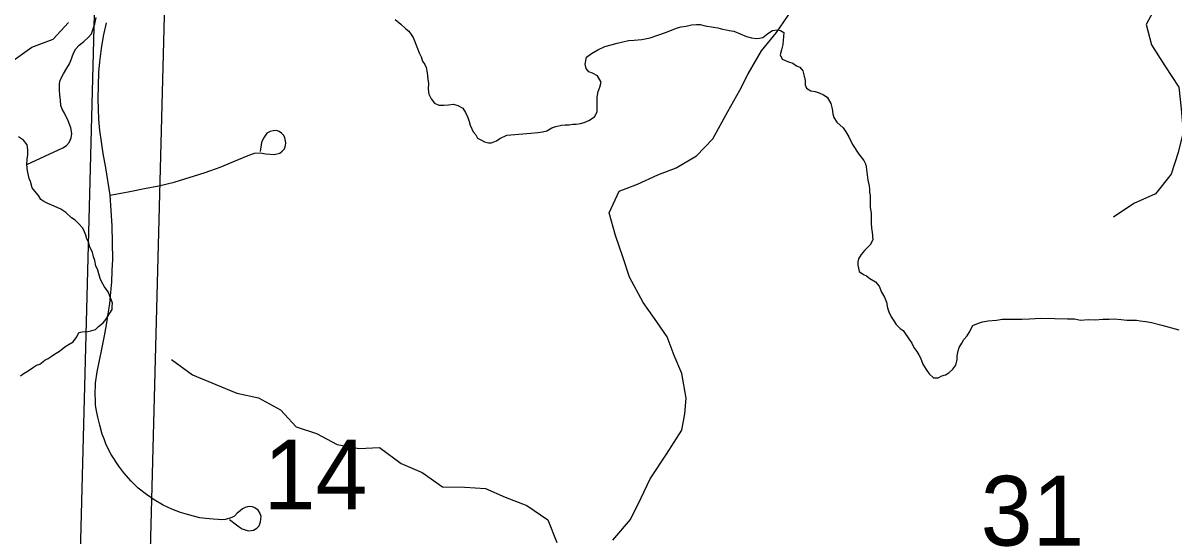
# Model space of a CAD drawing. Extents: x -21.1 to 50.3, y 0 to 22.1.
# Drawn here: x 2.692 to 3.383, y 19.37 to 19.678 of the extents above; entities that cross this region are included whole.
import ezdxf

# ---------------------------------------------------------------- set-up
doc = ezdxf.new("R2010")
doc.units = 0
for name, color, linetype in [('GM_X_Minor_River', 7, 'Continuous'), ('GM_X_Section', 7, 'Continuous'), ('GM_X_Section_Text', 7, 'Continuous'), ('GM_X_Township_Road', 7, 'Continuous')]:
    doc.layers.add(name, color=color, linetype=linetype)

msp = doc.modelspace()

# ---------------------------------------------------------------- linework, layer by layer
at = {"layer": 'GM_X_Minor_River'}
for points in [[(3.39957, 19.77915), (3.39901, 19.77155), (3.39523, 19.75823), (3.38687, 19.74681), (3.38726, 19.7373), (3.38918, 19.72742), (3.39186, 19.71449), (3.38237, 19.70193), (3.37326, 19.68937), (3.36681, 19.67719), (3.36987, 19.66502), (3.37788, 19.65248), (3.38627, 19.63956), (3.38781, 19.62663), (3.38897, 19.61256), (3.38594, 19.60039), (3.38178, 19.58745), (3.37228, 19.57565), (3.35935, 19.56993), (3.34719, 19.56155)], [(3.04644, 19.36782), (3.05706, 19.38033), (3.06351, 19.39323), (3.06882, 19.40461), (3.07869, 19.4194), (3.08779, 19.43382), (3.08969, 19.44368), (3.09046, 19.45316), (3.08781, 19.46795), (3.08327, 19.47857), (3.0791, 19.48994), (3.07153, 19.50094), (3.06471, 19.51043), (3.05638, 19.52559), (3.05259, 19.53735), (3.04805, 19.55062), (3.04427, 19.56428), (3.05034, 19.57718), (3.06133, 19.58135), (3.07347, 19.58704), (3.08446, 19.59121), (3.0966, 19.59842), (3.10646, 19.60866), (3.11556, 19.62497), (3.12277, 19.63787), (3.1277, 19.64773), (3.13567, 19.66138), (3.14477, 19.67238), (3.1535, 19.68528)], [(2.68421, 19.65412), (2.69748, 19.6636), (2.71037, 19.66853), (2.71947, 19.6784)], [(2.69461, 19.59333), (2.71609, 19.60318), (2.7184, 19.60466), (2.71995, 19.60652), (2.72114, 19.60916), (2.72157, 19.61181), (2.72088, 19.61524), (2.71943, 19.61945), (2.71724, 19.62405), (2.71576, 19.62635), (2.71504, 19.62864), (2.71472, 19.63169), (2.7144, 19.63511), (2.71407, 19.63778), (2.71411, 19.63967), (2.71414, 19.64157), (2.71457, 19.64384), (2.71654, 19.64761), (2.7185, 19.65099), (2.72007, 19.65362), (2.72127, 19.65663), (2.72206, 19.65851), (2.72286, 19.6604), (2.72404, 19.66266), (2.72599, 19.6649), (2.72869, 19.66713), (2.73139, 19.66936), (2.73334, 19.6716), (2.73535, 19.67764), (2.73618, 19.68142)], [(2.91565, 19.68014), (2.91904, 19.67743), (2.92205, 19.67472), (2.92393, 19.67318), (2.92542, 19.67126), (2.92654, 19.66934), (2.92727, 19.66743), (2.93021, 19.66016), (2.93132, 19.65786), (2.93205, 19.65519), (2.93354, 19.65326), (2.93428, 19.65135), (2.935, 19.6483), (2.93532, 19.64449), (2.93567, 19.64183), (2.93562, 19.6384), (2.93596, 19.63536), (2.93745, 19.63267), (2.93931, 19.62998), (2.94195, 19.62881), (2.945, 19.62876), (2.94766, 19.62911), (2.95071, 19.62945), (2.95337, 19.62865), (2.95639, 19.62709), (2.95787, 19.6244), (2.95935, 19.62134), (2.96008, 19.61905), (2.96081, 19.61676), (2.96266, 19.61293), (2.96415, 19.61101), (2.96527, 19.60909), (2.96753, 19.60792), (2.96942, 19.60675), (2.9717, 19.60634), (2.9736, 19.60631), (2.97666, 19.60741), (2.97858, 19.6089), (2.98279, 19.61075), (2.99726, 19.61207), (3.00145, 19.61239), (3.00412, 19.61274), (3.00679, 19.61346), (3.00986, 19.61532), (3.01215, 19.61605), (3.01558, 19.61676), (3.01787, 19.61711), (3.02015, 19.61708), (3.02244, 19.61743), (3.02434, 19.6174), (3.02701, 19.61775), (3.0293, 19.61848), (3.03198, 19.61958), (3.03543, 19.62181), (3.03699, 19.62484), (3.03702, 19.62712), (3.03707, 19.63054), (3.03711, 19.63358), (3.03754, 19.637), (3.03872, 19.63965), (3.03952, 19.64268), (3.03729, 19.64651), (3.03427, 19.64808), (3.032, 19.64887), (3.0305, 19.65079), (3.02978, 19.65346), (3.03059, 19.65764), (3.03367, 19.65987), (3.0375, 19.6621), (3.04171, 19.66395), (3.04553, 19.66504), (3.04897, 19.66613), (3.0524, 19.66684), (3.05584, 19.66756), (3.05926, 19.66789), (3.06383, 19.66821), (3.06879, 19.66928), (3.07338, 19.67074), (3.07873, 19.67257), (3.08217, 19.67404), (3.08523, 19.67514), (3.08752, 19.67587), (3.09057, 19.67621), (3.09362, 19.67693), (3.09667, 19.67726), (3.09895, 19.67723), (3.10198, 19.67643), (3.10691, 19.6756), (3.10957, 19.67518), (3.11222, 19.67439), (3.1145, 19.67398), (3.1164, 19.67357), (3.11905, 19.67315), (3.12283, 19.67158)], [(3.12283, 19.67158), (3.12662, 19.67), (3.12965, 19.6692), (3.13269, 19.66878), (3.13459, 19.66913), (3.1365, 19.66949), (3.13957, 19.67173), (3.14226, 19.67359), (3.14531, 19.67393), (3.1472, 19.67353), (3.14909, 19.67236), (3.14861, 19.66514), (3.14781, 19.66211), (3.14701, 19.65907), (3.14811, 19.6564), (3.15189, 19.65482), (3.15454, 19.65403), (3.15681, 19.65247), (3.1587, 19.65169), (3.16057, 19.64938), (3.16128, 19.64633), (3.16201, 19.64365), (3.16197, 19.64099), (3.16271, 19.63908), (3.16535, 19.63752), (3.16801, 19.6371), (3.17028, 19.63631), (3.17292, 19.63513), (3.17518, 19.63358), (3.17741, 19.62975), (3.17813, 19.62669), (3.17847, 19.62365), (3.1792, 19.62136), (3.18106, 19.61867), (3.18482, 19.61519), (3.18631, 19.61289), (3.18817, 19.60982), (3.19039, 19.60523), (3.19411, 19.59947), (3.1971, 19.59562), (3.19822, 19.59371), (3.19857, 19.5918), (3.1996, 19.5838), (3.20032, 19.58036), (3.20067, 19.57846), (3.20065, 19.57656), (3.201, 19.57465), (3.20096, 19.57161), (3.2009, 19.56743), (3.20162, 19.56399), (3.20157, 19.56095), (3.20154, 19.55829), (3.20187, 19.55486), (3.20222, 19.55257), (3.20254, 19.54801), (3.20097, 19.54498), (3.1975, 19.54161), (3.19557, 19.53935), (3.19402, 19.53671), (3.19361, 19.53482), (3.19358, 19.53291), (3.19394, 19.53101), (3.19429, 19.5291), (3.19692, 19.52716), (3.19882, 19.52638), (3.2007, 19.52483), (3.20409, 19.52288), (3.20634, 19.52019), (3.20781, 19.51674), (3.20967, 19.51367), (3.21077, 19.51062), (3.21149, 19.50718), (3.21222, 19.50489), (3.21369, 19.50183), (3.21518, 19.49953), (3.21667, 19.49722), (3.21892, 19.49491), (3.22081, 19.49374), (3.22192, 19.49183), (3.22603, 19.48606), (3.22713, 19.48339), (3.22901, 19.48108), (3.23012, 19.47916), (3.23123, 19.47724), (3.2327, 19.47342), (3.23456, 19.47035), (3.23643, 19.46766), (3.23906, 19.46534), (3.24172, 19.46531), (3.24402, 19.46642), (3.24631, 19.46715), (3.24823, 19.46826), (3.25054, 19.47051), (3.25247, 19.47277), (3.25328, 19.47618), (3.25331, 19.47846), (3.25373, 19.4815), (3.25452, 19.48339), (3.25608, 19.48603), (3.25725, 19.48829), (3.25918, 19.49055)], [(2.74115, 19.51992), (2.73931, 19.52299), (2.73858, 19.52491), (2.73787, 19.52758), (2.73715, 19.52987), (2.73606, 19.53255), (2.73536, 19.5356), (2.73464, 19.53789), (2.73393, 19.54056), (2.73247, 19.54363), (2.73176, 19.5463), (2.73066, 19.5486), (2.72994, 19.55089), (2.72922, 19.5528), (2.72812, 19.5551), (2.72551, 19.55781), (2.72364, 19.55975), (2.72139, 19.56131), (2.71803, 19.56441), (2.71502, 19.56636), (2.71088, 19.56834), (2.7071, 19.56993), (2.70484, 19.57111), (2.70297, 19.57228), (2.70149, 19.57459), (2.69926, 19.57729), (2.69777, 19.57922), (2.6967, 19.58303), (2.69598, 19.58494), (2.69492, 19.58952), (2.69461, 19.59333), (2.69467, 19.59636), (2.6951, 19.59901), (2.69516, 19.60205), (2.69483, 19.60509), (2.6926, 19.60779), (2.6896, 19.60975)], [(2.69073, 19.46655), (2.69303, 19.46803), (2.69534, 19.46951), (2.69804, 19.47135), (2.70035, 19.47283), (2.70226, 19.47355), (2.70535, 19.47578), (2.70727, 19.47688), (2.70919, 19.47798), (2.71112, 19.47947), (2.7142, 19.48131), (2.71728, 19.48391), (2.71997, 19.48538), (2.72228, 19.48685), (2.72462, 19.48985), (2.72581, 19.49248), (2.72772, 19.49283), (2.73114, 19.49314), (2.73305, 19.49349), (2.73573, 19.4942), (2.73766, 19.49606), (2.74036, 19.49829), (2.74192, 19.50016), (2.74584, 19.50616), (2.74587, 19.50806), (2.74591, 19.50996), (2.74519, 19.51225), (2.74337, 19.51684), (2.74115, 19.51992)], [(3.25918, 19.49055), (3.26035, 19.49244), (3.26269, 19.49659), (3.26613, 19.49806), (3.26842, 19.49879), (3.27186, 19.49951), (3.27681, 19.49982), (3.28024, 19.50053), (3.2829, 19.50049), (3.29203, 19.50037), (3.2966, 19.50069), (3.30345, 19.50097), (3.31181, 19.50086), (3.31942, 19.50075), (3.3236, 19.50069), (3.32739, 19.49988), (3.33196, 19.5002), (3.33615, 19.50014), (3.34072, 19.50046), (3.34452, 19.50041), (3.34757, 19.50074), (3.35174, 19.50031), (3.35516, 19.49988), (3.35859, 19.49983), (3.36087, 19.4998), (3.36314, 19.49939), (3.36656, 19.49896), (3.36998, 19.49854), (3.37604, 19.49693), (3.38627, 19.49413)], [(2.78136, 19.47634), (2.79401, 19.46707), (2.80811, 19.46125), (2.82068, 19.45615), (2.83359, 19.45334), (2.84696, 19.44599), (2.85622, 19.4359), (2.86839, 19.43194), (2.88099, 19.42533), (2.89389, 19.4229), (2.90637, 19.4235), (2.9194, 19.41386), (2.93198, 19.40839), (2.94423, 19.39987), (2.95747, 19.39972), (2.96997, 19.3988), (2.98179, 19.3937), (2.99474, 19.38861), (3.00737, 19.3801), (3.01291, 19.36654)]]:
    msp.add_lwpolyline(points, dxfattribs=at)
at = {"layer": 'GM_X_Section'}
for points in [[(3.82397, 20.01814), (3.83539, 19.00471), (3.80166, 19.0044), (2.75941, 19.00342), (2.78495, 19.98), (2.78619, 20.01563)], [(3.78068, 19.96762), (3.7921, 18.95419), (3.75837, 18.95389), (2.71612, 18.9529), (2.74167, 19.92948), (2.74291, 19.96511)]]:
    msp.add_lwpolyline(points, close=True, dxfattribs=at)
at = {"layer": 'GM_X_Township_Road'}
for points in [[(2.81617, 19.38037), (2.82045, 19.37702), (2.82204, 19.37586), (2.8239, 19.37472), (2.82567, 19.3741), (2.82744, 19.37357), (2.82925, 19.37359), (2.83071, 19.37383), (2.83266, 19.37498), (2.83399, 19.37655), (2.83454, 19.37772), (2.83496, 19.37897), (2.83513, 19.38047), (2.83523, 19.38206), (2.83452, 19.38427), (2.83345, 19.38586), (2.83151, 19.38737), (2.83, 19.38781), (2.82832, 19.38799), (2.82699, 19.3879), (2.82558, 19.38746), (2.82408, 19.38666), (2.82257, 19.38542), (2.82089, 19.384), (2.8193, 19.38233), (2.8177, 19.38153), (2.81594, 19.38082), (2.81356, 19.38033), (2.81151, 19.38011), (2.80939, 19.38021), (2.80644, 19.38041), (2.80196, 19.38089), (2.79842, 19.38136), (2.79453, 19.38218), (2.79098, 19.38325), (2.78674, 19.38443), (2.78155, 19.38643), (2.77636, 19.38891), (2.77093, 19.39198), (2.76633, 19.39528), (2.76149, 19.39905), (2.75713, 19.4033), (2.75276, 19.40825), (2.74969, 19.41226), (2.7451, 19.41922), (2.74332, 19.42265), (2.74203, 19.42571), (2.74109, 19.42797), (2.73984, 19.43152), (2.73831, 19.43695), (2.7371, 19.44161), (2.73631, 19.44541), (2.73587, 19.44886), (2.73569, 19.4524), (2.7356, 19.45487), (2.73587, 19.46213), (2.73684, 19.46885), (2.7379, 19.47469), (2.73976, 19.48345), (2.74126, 19.49044), (2.74241, 19.49699), (2.74347, 19.50362), (2.74436, 19.50973), (2.74507, 19.51663), (2.7456, 19.52273), (2.74587, 19.52964), (2.74616, 19.53617), (2.7457, 19.55635), (2.74467, 19.57481), (2.74192, 19.59132), (2.74034, 19.59994), (2.73929, 19.60692), (2.73837, 19.61357), (2.73779, 19.62022), (2.73753, 19.62666), (2.73733, 19.63238), (2.73768, 19.64866), (2.73837, 19.65474), (2.7394, 19.66288), (2.74066, 19.67022), (2.74238, 19.67813)], [(2.74467, 19.57481), (2.75637, 19.5771), (2.76528, 19.57879), (2.7738, 19.58054), (2.78297, 19.58261), (2.80167, 19.58845), (2.81061, 19.59167), (2.82162, 19.59625), (2.82745, 19.59861), (2.83129, 19.59995), (2.8347, 19.60019), (2.83813, 19.59968), (2.84299, 19.5993), (2.84647, 19.60009), (2.84797, 19.60118), (2.84934, 19.60255), (2.84988, 19.6046), (2.85016, 19.60624), (2.84947, 19.60925), (2.84879, 19.61062), (2.84742, 19.61212), (2.84606, 19.61308), (2.84442, 19.61363), (2.8425, 19.61349), (2.84072, 19.61308), (2.83867, 19.61212), (2.83662, 19.60898), (2.83553, 19.60638), (2.8347, 19.60111)]]:
    msp.add_lwpolyline(points, dxfattribs=at)

# ---------------------------------------------------------------- texts
at = {"layer": 'GM_X_Section_Text'}
for s, p in [('14', (2.83679, 19.3863)), ('31', (3.26735, 19.36463))]:
    msp.add_text(s, height=0.041856, rotation=0.00001, dxfattribs=at).set_placement(p)

doc.saveas('drawing.dxf')
